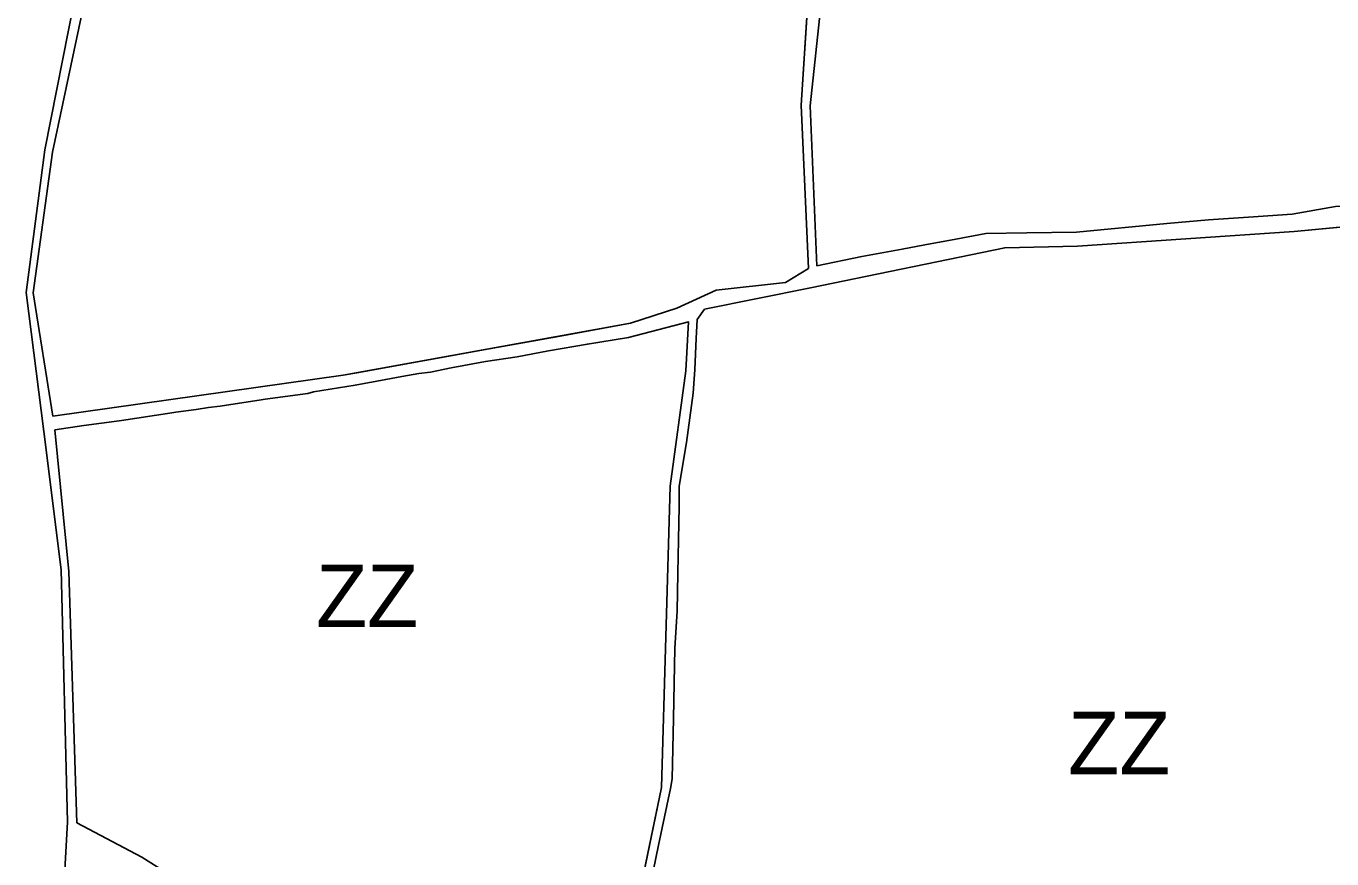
# Model space of a CAD drawing. Extents: x -555509 to -553005, y -1186756 to -1182560.
# Drawn here: x -555043.1 to -554751, y -1184851.2 to -1184664.9 of the extents above; entities that cross this region are included whole.
import ezdxf

# ---------------------------------------------------------------- set-up
doc = ezdxf.new("R2010")
doc.units = 0
for name, color, linetype in [('Level 26', 7, 'Continuous'), ('Level 59', 7, 'Continuous'), ('OBRYS_PLOCH', 7, 'Continuous'), ('stav_ZZ', 7, 'Continuous')]:
    doc.layers.add(name, color=color, linetype=linetype)

msp = doc.modelspace()

# ---------------------------------------------------------------- linework, layer by layer
at = {"layer": 'Level 26'}
for p, q in [((-555037.18, -1184693.13), (-555030.02, -1184659.42)), ((-554759.48, -1184710.88), (-554707.77, -1184705.96)), ((-554868.1, -1184719.17), (-554873.22, -1184722.29)), ((-554873.22, -1184722.29), (-554888.73, -1184723.98)), ((-554888.73, -1184723.98), (-554897.56, -1184728.03)), ((-554897.56, -1184728.03), (-554907.89, -1184731.4)), ((-554893, -1184730.57), (-554891.35, -1184728.22)), ((-554908.36, -1184734.59), (-554894.93, -1184731.08)), ((-554933.28, -1184738.92), (-554926.29, -1184737.58)), ((-554959.1, -1184743.34), (-554955.29, -1184742.67)), ((-554969.53, -1184745.26), (-554962.65, -1184743.97)), ((-554962.65, -1184743.97), (-554959.1, -1184743.34)), ((-555002.31, -1184750.25), (-554999.71, -1184749.95)), ((-555036.69, -1184755.24), (-555030.18, -1184754.28)), ((-554900.96, -1184835.23), (-554907.71, -1184867.66)), ((-555033.83, -1184842.95), (-555034.44, -1184853.76)), ((-555017.2, -1184850.85), (-555031.78, -1184843.13)), ((-555004.96, -1184858.5), (-555017.2, -1184850.85))]:
    msp.add_line(p, q, dxfattribs=at)
for points in [[(-554866.23, -1184718.52), (-554867.73, -1184682.78), (-554865.2, -1184658.98), (-554864.67, -1184625.33), (-554862.57, -1184593.87), (-554857.78, -1184552.7)], [(-555018.42, -1184595.69), (-555032.26, -1184659), (-555038.96, -1184692.59), (-555043.11, -1184724.5)], [(-554868.32, -1184624.96), (-554868.18, -1184658.19), (-554869.72, -1184682.65), (-554868.1, -1184719.17)], [(-555037.17, -1184752.21), (-555041.51, -1184724.58), (-555037.18, -1184693.13)], [(-554697.96, -1184701.13), (-554705.66, -1184703.17), (-554712.5, -1184704.91), (-554721.4, -1184705.02), (-554736.82, -1184705.2), (-554750.23, -1184705.31), (-554759.91, -1184706.97), (-554769.66, -1184707.68), (-554778.67, -1184708.28), (-554787.94, -1184709.12), (-554808.14, -1184710.99), (-554819.25, -1184711.16), (-554828.48, -1184711.34), (-554835.19, -1184712.6), (-554842.1, -1184713.87), (-554847.14, -1184714.82), (-554856.21, -1184716.49), (-554866.23, -1184718.52)], [(-554891.35, -1184728.22), (-554867.64, -1184723.45), (-554824.23, -1184714.52), (-554807.91, -1184714.14), (-554759.48, -1184710.88)], [(-555043.11, -1184724.5), (-555039.16, -1184755.62), (-555035.24, -1184786.57), (-555033.83, -1184842.95)], [(-554907.89, -1184731.4), (-554972.2, -1184743.03), (-555037.17, -1184752.21)], [(-554918.99, -1184900.42), (-554912.48, -1184887.91), (-554906.23, -1184870.29), (-554905.76, -1184868.08), (-554901.67, -1184848.15), (-554900.33, -1184841.83), (-554898.98, -1184835.49), (-554898.57, -1184833.28), (-554898.28, -1184819.78), (-554898.12, -1184811.92), (-554897.98, -1184804.08), (-554897.5, -1184795.77), (-554897.32, -1184787.32), (-554897.17, -1184779.83), (-554897.06, -1184772.33), (-554897.04, -1184767.82), (-554895.43, -1184758.04), (-554893.91, -1184747.05), (-554893.56, -1184741.74), (-554893.23, -1184734.84), (-554893, -1184730.57)], [(-554894.93, -1184731.08), (-554895.53, -1184742.06), (-554899.06, -1184767.81), (-554900.96, -1184835.23)], [(-554926.29, -1184737.58), (-554917.56, -1184736.06), (-554908.36, -1184734.59)], [(-554955.29, -1184742.67), (-554952.68, -1184742.31), (-554948.01, -1184741.34), (-554940.32, -1184739.96), (-554933.28, -1184738.92)], [(-554999.71, -1184749.95), (-554990.57, -1184748.5), (-554989.63, -1184748.41), (-554980.08, -1184747.09), (-554978.82, -1184746.76), (-554969.53, -1184745.26)], [(-555021.75, -1184753.12), (-555010.55, -1184751.45), (-555009.6, -1184751.29), (-555005.11, -1184750.65), (-555002.31, -1184750.25)], [(-555030.18, -1184754.28), (-555022.31, -1184753.2), (-555021.75, -1184753.12)], [(-555031.78, -1184843.13), (-555033.56, -1184786.91), (-555036.69, -1184755.24)]]:
    msp.add_lwpolyline(points, dxfattribs=at)
at = {"layer": 'OBRYS_PLOCH'}
for p, q in [((-555037.18, -1184693.13), (-555030.02, -1184659.42)), ((-554778.67, -1184708.28), (-554769.66, -1184707.68)), ((-554759.48, -1184710.88), (-554707.77, -1184705.96)), ((-554819.25, -1184711.16), (-554808.14, -1184710.99)), ((-554868.1, -1184719.17), (-554873.22, -1184722.29)), ((-554873.22, -1184722.29), (-554888.73, -1184723.98)), ((-554888.73, -1184723.98), (-554897.56, -1184728.03)), ((-554897.56, -1184728.03), (-554907.89, -1184731.4)), ((-554893, -1184730.57), (-554891.35, -1184728.22)), ((-554908.36, -1184734.59), (-554894.93, -1184731.08)), ((-554933.28, -1184738.92), (-554926.29, -1184737.58)), ((-554959.1, -1184743.34), (-554955.29, -1184742.67)), ((-554969.53, -1184745.26), (-554962.65, -1184743.97)), ((-554962.65, -1184743.97), (-554959.1, -1184743.34)), ((-555010.55, -1184751.45), (-555021.75, -1184753.12)), ((-555002.31, -1184750.25), (-555005.11, -1184750.65)), ((-554999.71, -1184749.95), (-555002.31, -1184750.25)), ((-555002.31, -1184750.25), (-554999.71, -1184749.95)), ((-555030.18, -1184754.28), (-555036.69, -1184755.24)), ((-555036.69, -1184755.24), (-555030.18, -1184754.28)), ((-554900.96, -1184835.23), (-554907.71, -1184867.66)), ((-555033.83, -1184842.95), (-555034.44, -1184853.76)), ((-555031.78, -1184843.13), (-555017.2, -1184850.85)), ((-555017.2, -1184850.85), (-555031.78, -1184843.13)), ((-555017.2, -1184850.85), (-555004.96, -1184858.5)), ((-555004.96, -1184858.5), (-555017.2, -1184850.85))]:
    msp.add_line(p, q, dxfattribs=at)
for points in [[(-554866.23, -1184718.52), (-554867.73, -1184682.78), (-554865.2, -1184658.98), (-554864.67, -1184625.33), (-554862.57, -1184593.87), (-554857.78, -1184552.7)], [(-555018.42, -1184595.69), (-555032.26, -1184659), (-555038.96, -1184692.59), (-555043.11, -1184724.5)], [(-554868.32, -1184624.96), (-554868.18, -1184658.19), (-554869.72, -1184682.65), (-554868.1, -1184719.17)], [(-554865.2, -1184658.98), (-554867.73, -1184682.78), (-554866.23, -1184718.52)], [(-555037.17, -1184752.21), (-555041.51, -1184724.58), (-555037.18, -1184693.13)], [(-554697.96, -1184701.13), (-554705.66, -1184703.17), (-554712.5, -1184704.91), (-554721.4, -1184705.02), (-554736.82, -1184705.2), (-554750.23, -1184705.31), (-554759.91, -1184706.97), (-554769.66, -1184707.68), (-554778.67, -1184708.28), (-554787.94, -1184709.12), (-554808.14, -1184710.99), (-554819.25, -1184711.16), (-554828.48, -1184711.34), (-554835.19, -1184712.6), (-554842.1, -1184713.87), (-554847.14, -1184714.82), (-554856.21, -1184716.49), (-554866.23, -1184718.52)], [(-554769.66, -1184707.68), (-554759.91, -1184706.97), (-554750.23, -1184705.31), (-554736.82, -1184705.2), (-554721.4, -1184705.02)], [(-554707.77, -1184705.96), (-554759.48, -1184710.88), (-554807.91, -1184714.14), (-554824.23, -1184714.52), (-554867.64, -1184723.45), (-554891.35, -1184728.22), (-554893, -1184730.57), (-554893.23, -1184734.84), (-554893.56, -1184741.74), (-554893.91, -1184747.05), (-554895.43, -1184758.04), (-554897.04, -1184767.82), (-554897.06, -1184772.33), (-554897.17, -1184779.83), (-554897.32, -1184787.32), (-554897.5, -1184795.77), (-554897.98, -1184804.08), (-554898.12, -1184811.92), (-554898.28, -1184819.78), (-554898.57, -1184833.28), (-554898.98, -1184835.49), (-554900.33, -1184841.83), (-554901.67, -1184848.15), (-554905.76, -1184868.08)], [(-554891.35, -1184728.22), (-554867.64, -1184723.45), (-554824.23, -1184714.52), (-554807.91, -1184714.14), (-554759.48, -1184710.88)], [(-554808.14, -1184710.99), (-554787.94, -1184709.12), (-554778.67, -1184708.28)], [(-554866.23, -1184718.52), (-554856.21, -1184716.49), (-554847.14, -1184714.82), (-554842.1, -1184713.87), (-554835.19, -1184712.6), (-554828.48, -1184711.34), (-554819.25, -1184711.16)], [(-555043.11, -1184724.5), (-555039.16, -1184755.62), (-555035.24, -1184786.57), (-555033.83, -1184842.95)], [(-554907.89, -1184731.4), (-554972.2, -1184743.03), (-555037.17, -1184752.21)], [(-554918.99, -1184900.42), (-554913.45, -1184887.69), (-554907.71, -1184867.66), (-554900.96, -1184835.23), (-554899.06, -1184767.81), (-554895.53, -1184742.06), (-554894.93, -1184731.08), (-554908.36, -1184734.59), (-554917.56, -1184736.06), (-554926.29, -1184737.58), (-554933.28, -1184738.92), (-554940.32, -1184739.96), (-554948.01, -1184741.34), (-554952.68, -1184742.31), (-554955.29, -1184742.67), (-554959.1, -1184743.34), (-554962.65, -1184743.97), (-554969.53, -1184745.26), (-554978.82, -1184746.76), (-554980.08, -1184747.09), (-554989.63, -1184748.41), (-554990.57, -1184748.5), (-554999.71, -1184749.95)], [(-554918.99, -1184900.42), (-554912.48, -1184887.91), (-554906.23, -1184870.29), (-554905.76, -1184868.08), (-554901.67, -1184848.15), (-554900.33, -1184841.83), (-554898.98, -1184835.49), (-554898.57, -1184833.28), (-554898.28, -1184819.78), (-554898.12, -1184811.92), (-554897.98, -1184804.08), (-554897.5, -1184795.77), (-554897.32, -1184787.32), (-554897.17, -1184779.83), (-554897.06, -1184772.33), (-554897.04, -1184767.82), (-554895.43, -1184758.04), (-554893.91, -1184747.05), (-554893.56, -1184741.74), (-554893.23, -1184734.84), (-554893, -1184730.57)], [(-554894.93, -1184731.08), (-554895.53, -1184742.06), (-554899.06, -1184767.81), (-554900.96, -1184835.23)], [(-554926.29, -1184737.58), (-554917.56, -1184736.06), (-554908.36, -1184734.59)], [(-554955.29, -1184742.67), (-554952.68, -1184742.31), (-554948.01, -1184741.34), (-554940.32, -1184739.96), (-554933.28, -1184738.92)], [(-554999.71, -1184749.95), (-554990.57, -1184748.5), (-554989.63, -1184748.41), (-554980.08, -1184747.09), (-554978.82, -1184746.76), (-554969.53, -1184745.26)], [(-555021.75, -1184753.12), (-555010.55, -1184751.45), (-555009.6, -1184751.29), (-555005.11, -1184750.65), (-555002.31, -1184750.25)], [(-555005.11, -1184750.65), (-555009.6, -1184751.29), (-555010.55, -1184751.45)], [(-555021.75, -1184753.12), (-555022.31, -1184753.2), (-555030.18, -1184754.28)], [(-555030.18, -1184754.28), (-555022.31, -1184753.2), (-555021.75, -1184753.12)], [(-555036.69, -1184755.24), (-555033.56, -1184786.91), (-555031.78, -1184843.13)], [(-555031.78, -1184843.13), (-555033.56, -1184786.91), (-555036.69, -1184755.24)]]:
    msp.add_lwpolyline(points, dxfattribs=at)
at = {"layer": 'stav_ZZ'}
for p, q in [((-554869.72, -1184682.65), (-554868.18, -1184658.19)), ((-555030.02, -1184659.42), (-555037.18, -1184693.13)), ((-554868.1, -1184719.17), (-554869.72, -1184682.65)), ((-555037.18, -1184693.13), (-555041.51, -1184724.58)), ((-554778.67, -1184708.28), (-554769.66, -1184707.68)), ((-554819.25, -1184711.16), (-554808.14, -1184710.99)), ((-554873.22, -1184722.29), (-554868.1, -1184719.17)), ((-554888.73, -1184723.98), (-554873.22, -1184722.29)), ((-555041.51, -1184724.58), (-555037.17, -1184752.21)), ((-554897.56, -1184728.03), (-554888.73, -1184723.98)), ((-554907.89, -1184731.4), (-554897.56, -1184728.03)), ((-554922.86, -1184734.1), (-554907.89, -1184731.4)), ((-554925.78, -1184734.63), (-554922.86, -1184734.1)), ((-554969.17, -1184742.48), (-554939.51, -1184737.12)), ((-554939.51, -1184737.12), (-554925.78, -1184734.63)), ((-555037.17, -1184752.21), (-554972.2, -1184743.03)), ((-554972.2, -1184743.03), (-554969.17, -1184742.48)), ((-555010.55, -1184751.45), (-555021.75, -1184753.12)), ((-555002.31, -1184750.25), (-555005.11, -1184750.65)), ((-554999.71, -1184749.95), (-555002.31, -1184750.25)), ((-555030.18, -1184754.28), (-555036.69, -1184755.24)), ((-555031.78, -1184843.13), (-555017.2, -1184850.85)), ((-555017.2, -1184850.85), (-555004.96, -1184858.5))]:
    msp.add_line(p, q, dxfattribs=at)
for points in [[(-554865.2, -1184658.98), (-554867.73, -1184682.78), (-554866.23, -1184718.52)], [(-554769.66, -1184707.68), (-554759.91, -1184706.97), (-554750.23, -1184705.31), (-554736.82, -1184705.2), (-554721.4, -1184705.02)], [(-554707.77, -1184705.96), (-554759.48, -1184710.88), (-554807.91, -1184714.14), (-554824.23, -1184714.52), (-554867.64, -1184723.45), (-554891.35, -1184728.22), (-554893, -1184730.57), (-554893.23, -1184734.84), (-554893.56, -1184741.74), (-554893.91, -1184747.05), (-554895.43, -1184758.04), (-554897.04, -1184767.82), (-554897.06, -1184772.33), (-554897.17, -1184779.83), (-554897.32, -1184787.32), (-554897.5, -1184795.77), (-554897.98, -1184804.08), (-554898.12, -1184811.92), (-554898.28, -1184819.78), (-554898.57, -1184833.28), (-554898.98, -1184835.49), (-554900.33, -1184841.83), (-554901.67, -1184848.15), (-554905.76, -1184868.08)], [(-554808.14, -1184710.99), (-554787.94, -1184709.12), (-554778.67, -1184708.28)], [(-554866.23, -1184718.52), (-554856.21, -1184716.49), (-554847.14, -1184714.82), (-554842.1, -1184713.87), (-554835.19, -1184712.6), (-554828.48, -1184711.34), (-554819.25, -1184711.16)], [(-554918.99, -1184900.42), (-554913.45, -1184887.69), (-554907.71, -1184867.66), (-554900.96, -1184835.23), (-554899.06, -1184767.81), (-554895.53, -1184742.06), (-554894.93, -1184731.08), (-554908.36, -1184734.59), (-554917.56, -1184736.06), (-554926.29, -1184737.58), (-554933.28, -1184738.92), (-554940.32, -1184739.96), (-554948.01, -1184741.34), (-554952.68, -1184742.31), (-554955.29, -1184742.67), (-554959.1, -1184743.34), (-554962.65, -1184743.97), (-554969.53, -1184745.26), (-554978.82, -1184746.76), (-554980.08, -1184747.09), (-554989.63, -1184748.41), (-554990.57, -1184748.5), (-554999.71, -1184749.95)], [(-555005.11, -1184750.65), (-555009.6, -1184751.29), (-555010.55, -1184751.45)], [(-555021.75, -1184753.12), (-555022.31, -1184753.2), (-555030.18, -1184754.28)], [(-555036.69, -1184755.24), (-555033.56, -1184786.91), (-555031.78, -1184843.13)]]:
    msp.add_lwpolyline(points, dxfattribs=at)

# ---------------------------------------------------------------- texts
at = {"layer": 'Level 59'}
for p in [(-554978.26, -1184799.36), (-554810.04, -1184832.27)]:
    msp.add_text('ZZ', height=14, dxfattribs=at).set_placement(p)

doc.saveas('drawing.dxf')
